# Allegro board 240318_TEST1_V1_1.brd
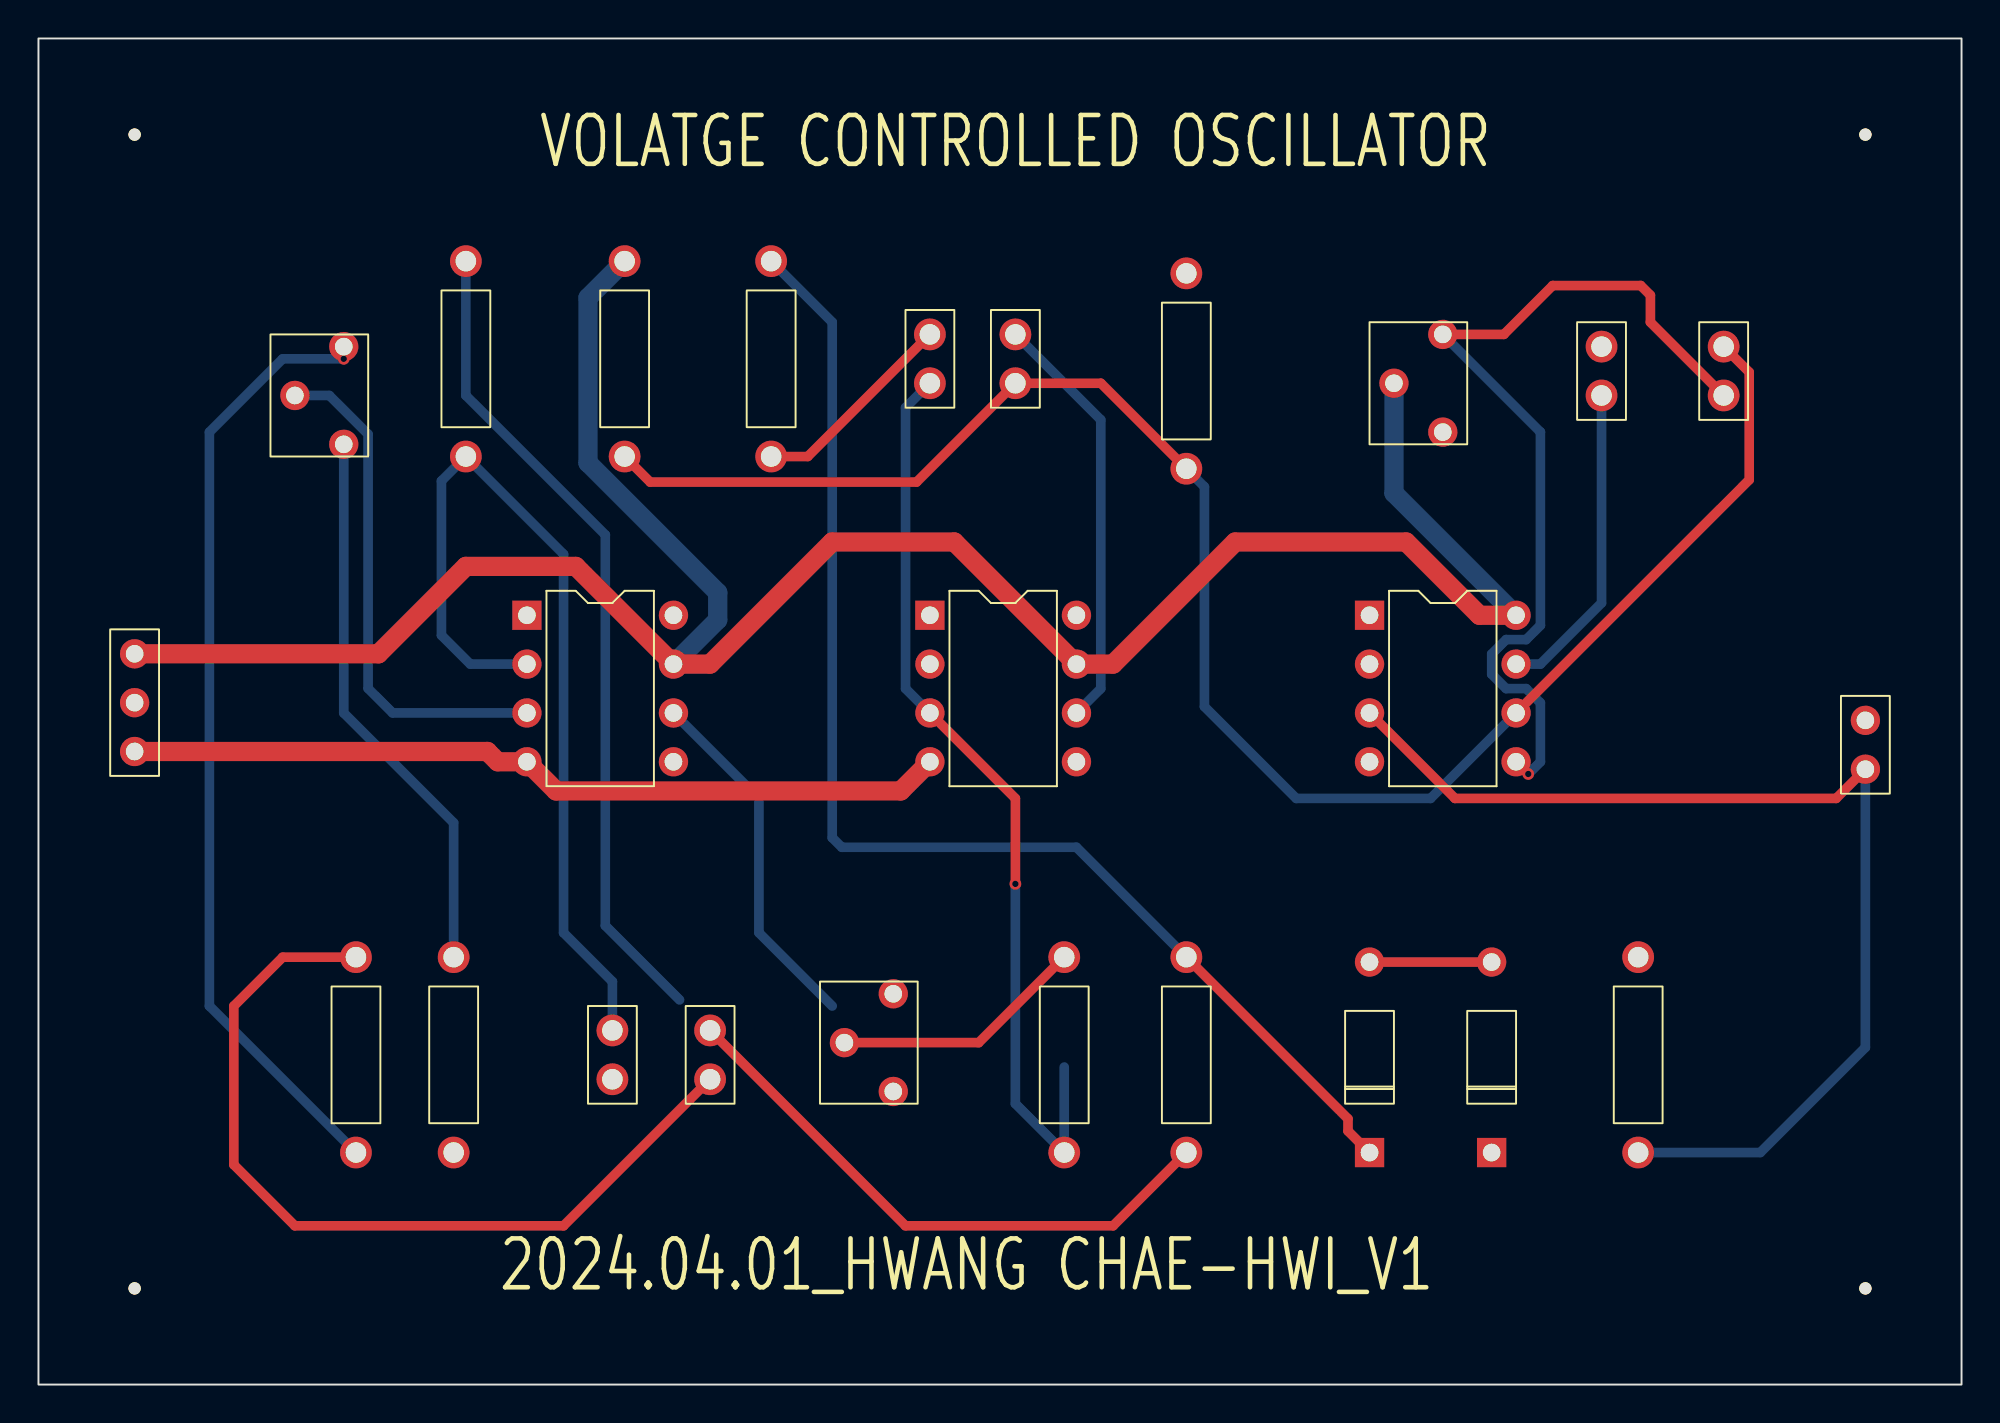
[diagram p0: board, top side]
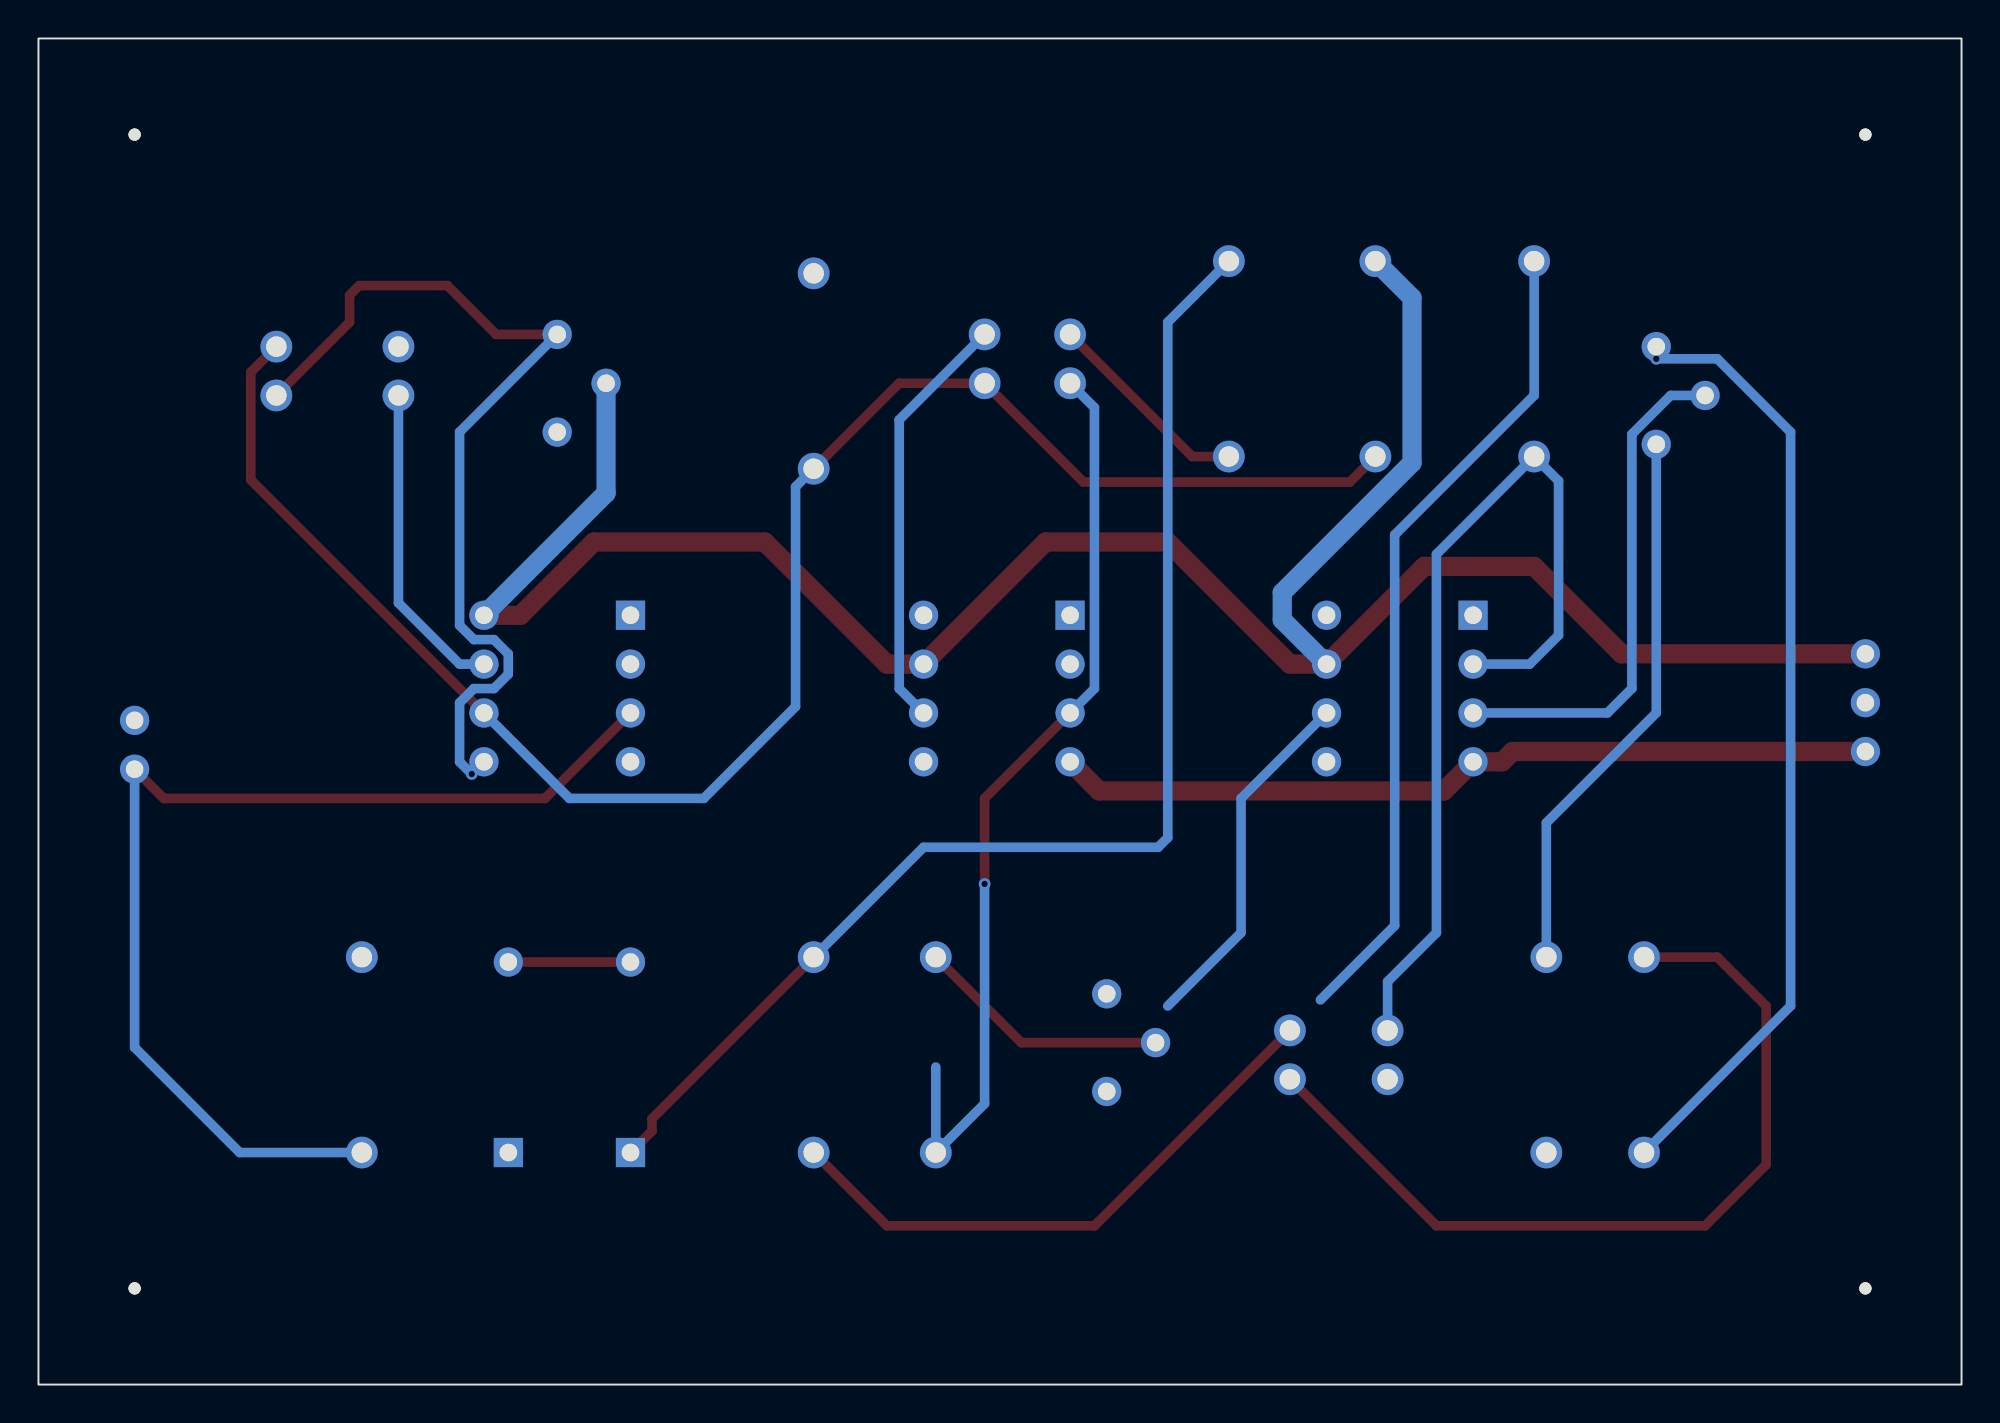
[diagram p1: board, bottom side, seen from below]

Outline 100 x 70 mm; copper layers: TOP, BOTTOM. Coordinates in mm from the lower left corner of the outline.
Outline path: rectangle 0,0 100,70

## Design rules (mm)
nets with their own width: min track width 1; nets +12V -12V GND

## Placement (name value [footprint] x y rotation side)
C1  2200pF  [CAPCK05]  46.35 52.07 0 top
C2  0.01uF  [CAPCK05]  87.63 51.44 0 top
C3  2200pF  [CAPCK05]  34.92 15.88 0 top
C4  0.1uF  [CAPCK05]  50.8 52.07 0 top
C5  0.1uF  [CAPCK05]  81.28 51.44 0 top
C6  2200pF  [CAPCK05]  29.84 15.88 0 top
D1  RD 3.9A  [DO41]  69.22 12.06 0 top
D2  RD 3.9A  [DO41]  75.56 12.06 0 top
J1  CON2  [JUMPER2]  95 32 90 top
J2  CON3  [JUMPER3]  5 38 270 top
NOREF  -  [unnamed]  95 65 0 top
NOREF#2  -  [unnamed]  95 5 0 top
NOREF#3  -  [unnamed]  5 5 0 top
NOREF#4  -  [unnamed]  5 65 0 top
R1  4.7k  [RES400]  16.51 12.06 0 top
R2  3,3K  [RES400]  30.48 48.26 0 top
R3  10K  [RES400]  53.34 12.06 0 top
R4  1K  [RES400]  38.1 48.26 0 top
R5  8,2K  [RES400]  59.69 47.62 0 top
R6  4.7k  [RES400]  83.19 12.06 0 top
R7  12K  [RES400]  22.23 48.26 0 top
R8  12K  [RES400]  59.69 12.06 0 top
R9  10K  [RES400]  21.59 12.06 0 top
U1  LM741  [DIP8_3]  25.4 40.01 0 top
U2  LM741  [DIP8_3]  46.35 40.01 0 top
U3  LM566C  [DIP8_3]  69.22 40.01 0 top
VR1  4.7K  [RESADJ]  73.03 54.61 0 top
VR2  10k  [RESADJ]  15.88 53.98 0 top
VR3  2K  [RESADJ]  44.45 20.32 0 top

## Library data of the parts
C1-C6 = CAP NP: Tolerance: ***; User Part Number: ***
D1 D2 = DIODE ZENER
J1 = CON2: User Part Number: ***
J2 = CON3: User Part Number: ***
R1-R9 = R: Tolerance: ***; User Part Number: ***
U1 U2 = LM741_0: Tolerance: ***; User Part Number: ***
U3 = LM566C_3: Tolerance: ***; User Part Number: ***
VR1 VR3 = RESISTOR VAR 2: Tolerance: ***; User Part Number: ***
VR2 = RESISTOR VAR: Tolerance: ***; User Part Number: ***

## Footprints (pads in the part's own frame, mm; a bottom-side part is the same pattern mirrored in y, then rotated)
CAPCK05
  round 1.651 hole 1.067: 1(0,0) 2(0,2.54)
DIP8_3
  rect 1.524x1.524 hole 0.914: 1(0,0)
  round 1.524 hole 0.914: 2(0,-2.54) 3(0,-5.08) 4(0,-7.62) 5(7.62,-7.62) 6(7.62,-5.08) 7(7.62,-2.54) 8(7.62,0)
DO41
  rect 1.524x1.524 hole 0.914: 1(0,0)
  round 1.524 hole 0.914: 2(0,9.906)
JUMPER2
  round 1.524 hole 0.914: 1(0,0) 2(2.54,0)
JUMPER3
  round 1.524 hole 0.914: 1(0,0) 2(2.54,0) 3(5.08,0)
RES400
  round 1.651 hole 1.067: 1(0,0) 2(0,10.16)
RESADJ
  round 1.524 hole 0.914: 1(0,0) 2(-2.54,-2.54) 3(0,-5.08)
unnamed
  round 0.635 hole 3.175 unplated: (0,0)

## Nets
+12V: J2.1 R2.2 U1.7(V+) U2.7(V+) U3.8 VR1.2
-12V: J2.3 U1.4(V-) U2.4(V-)
GND: C5.2 C6.1 D2.1(CATHODE) J1.2 J2.2 R5.2 R6.2 R9.1 U2.2(-IN) U3.1
A1: C4.2 U2.6(OUT)
OUT: J1.1 R6.1 U3.3(SQWOUT)
N01144: R1.1 VR2.1(A)
N01158: U1.3(+IN) VR2.2(WIPER)
N01162: U1.6(OUT) VR3.1
N01166: C3.1 R1.2
N01173: C6.2 R7.1 U1.2(-IN)
N01186: R9.2 VR2.3(B)
N01206: C3.2 R7.2 R8.1
N01220: R3.2 VR3.2
N01242: C1.1 R3.1 U2.3(+IN)
N01254: C1.2 R4.1
N01261: D1.1(CATHODE) R4.2 R8.2
N01265: D1.2(ANODE) D2.2(ANODE)
N01354: C2.2 C4.1 R2.1 R5.1 U3.6(TRES)
N01358: C2.1 U3.5(MOD) VR1.1
N01436: C5.1 U3.7(TCAP)

Pads without a net: U1 1 5 8; U2 1 5 8; U3 2 4; VR1 3; VR3 3

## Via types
v1: diameter 0.61, hole 0.33, TOP to BOTTOM, 9 vias

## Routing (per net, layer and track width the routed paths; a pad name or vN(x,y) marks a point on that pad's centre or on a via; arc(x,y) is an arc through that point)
+12V: length 125.5
  TOP w1: U3.8 74.93,40.01 71.12,43.81 62.23,43.81 55.88,37.47 53.98,37.47 47.62,43.81 41.27,43.81 34.92,37.47 U1.7 27.94,42.55 22.23,42.55 17.68,38 J2.1
  BOTTOM w1: U1.7 35.32,39.77 35.32,41.18 28.57,47.93 28.57,56.52 R2.2 ; VR1.2 70.48,46.35 U3.8
-12V: length 42.8
  TOP w1: 46.35,32.38 44.84,30.87 26.92,30.87 25.4,32.38 23.88,32.38 23.35,32.92 J2.3
A1: length 22
  BOTTOM w0.5: C4.2 55.24,50.17 55.24,36.19 53.98,34.92
OUT: length 56.8
  TOP w0.5: 69.22,34.92 73.66,30.48 93.48,30.48 J1.1
  BOTTOM w0.5: J1.1 95,17.53 89.53,12.06 R6.1
N01144: length 49.8
  TOP w0.5: VR2.1 v1(15.88,53.34)
  BOTTOM w0.5: v1(15.88,53.34) 12.7,53.34 8.89,49.53 8.89,19.68 R1.1
N01158: length 26.6
  BOTTOM w0.5: VR2.2 15.13,51.44 17.14,49.42 17.14,36.2 18.41,34.92 25.4,34.92
N01162: length 18.7
  BOTTOM w0.5: 33.02,34.92 37.47,30.48 37.47,23.5 41.27,19.68
N01166: length 44.9
  TOP w0.5: v1(16.51,22.23) 12.7,22.23 10.16,19.68 10.16,11.43 13.34,8.26 27.3,8.26 C3.1
N01173: length 47.9
  BOTTOM w0.5: C6.2 29.84,20.95 27.3,23.5 27.3,43.18 R7.1 20.95,46.99 20.95,38.97 22.45,37.47 v1(25.4,37.47)
N01186: length 29
  BOTTOM w0.5: v1(21.59,22.23) 21.59,29.21 15.88,34.92 VR2.3
N01206: length 73.6
  TOP w0.5: C3.2 45.09,8.26 55.88,8.26 R8.1
  BOTTOM w0.5: 33.34,20 29.48,23.86 29.48,44.18 22.23,51.44 R7.2
N01220: length 13.3
  TOP w0.5: VR3.2 48.9,17.78 R3.2
N01242: length 48.4
  TOP w0.5: 46.35,34.92 50.8,30.48 v1(50.8,26.04)
  BOTTOM w0.5: v1(50.8,26.04) 50.8,14.61 R3.1 53.34,16.51 ; 46.35,34.92 45.09,36.19 45.09,50.8 C1.1
N01254: length 10.9
  TOP w0.5: C1.2 40.01,48.26 v1(38.1,48.26)
N01261: length 66.4
  TOP w0.5: R8.2 68.1,13.82 68.1,13.18 D1.1
  BOTTOM w0.5: R4.2 41.27,55.24 41.27,28.44 41.77,27.94 53.98,27.94 R8.2
N01265: length 6.3
  TOP w0.5: D1.2 D2.2
N01354: length 91.1
  TOP w0.5: 76.83,34.92 88.96,47.05 88.96,52.65 v1(87.63,53.98) ; v1(30.48,48.26) 31.81,46.93 45.66,46.93 C4.1 55.24,52.07 R5.1
  BOTTOM w0.5: R5.1 60.63,46.68 60.63,35.25 65.41,30.48 72.39,30.48 76.83,34.92
N01358: length 48.3
  TOP w0.5: 76.83,32.38 v1(77.47,31.75) ; VR1.1 76.2,54.61 78.74,57.15 83.32,57.15 83.82,56.65 83.82,55.24 C2.1
  BOTTOM w0.5: v1(77.47,31.75) 78.1,32.38 78.1,35.45 77.36,36.19 76.32,36.19 75.57,36.94 75.57,37.99 76.32,38.74 77.36,38.74 78.1,39.48 78.1,49.53 VR1.1
N01436: length 16.6
  BOTTOM w0.5: U3.7 78.1,37.47 81.28,40.64 C5.1

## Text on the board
Ref Des/Silkscreen Top: 2024.04.01_HWANG CHAE-HWI_V1 | VOLATGE CONTROLLED OSCILLATOR
